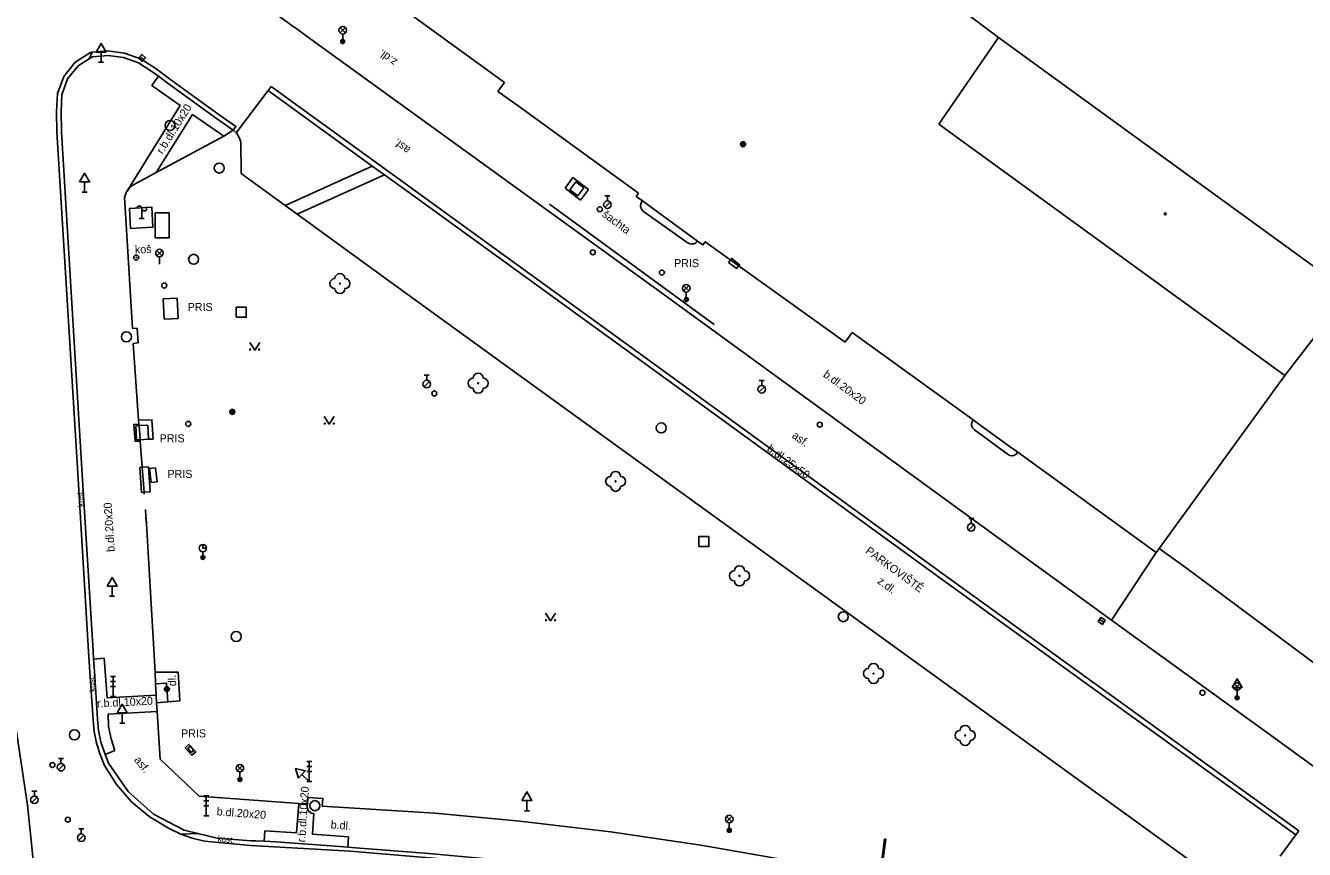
# Model space of a CAD drawing. Extents: x -599770 to -598493, y -1162076 to -1159209.
# Drawn here: x -599208.7 to -599144.8, y -1161563.7 to -1161522.6 of the extents above; entities that cross this region are included whole.
import ezdxf

# ---------------------------------------------------------------- set-up
doc = ezdxf.new("R2010")
doc.units = 0
doc.layers.add('Podklad', color=7, linetype='Continuous')

msp = doc.modelspace()

# ---------------------------------------------------------------- linework, layer by layer
at = {"layer": 'Podklad'}
for p, q in [((-599192.953, -1161522.94), (-599192.688, -1161522.675)), ((-599192.953, -1161522.675), (-599192.688, -1161522.94)), ((-599192.82, -1161522.995), (-599192.82, -1161523.37)), ((-599205.025, -1161524.41), (-599204.775, -1161524.41)), ((-599204.9, -1161523.901), (-599204.9, -1161524.41)), ((-599202.942, -1161524.105), (-599202.758, -1161524.275)), ((-599205.72, -1161530.381), (-599205.72, -1161530.89)), ((-599205.845, -1161530.89), (-599205.595, -1161530.89)), ((-599179.719, -1161531.656), (-599179.454, -1161531.391)), ((-599179.715, -1161531.082), (-599179.465, -1161531.082)), ((-599179.59, -1161531.332), (-599179.59, -1161531.082)), ((-599202.86, -1161532.21), (-599202.86, -1161531.71)), ((-599202.735, -1161532.21), (-599202.985, -1161532.21)), ((-599202.113, -1161534.07), (-599201.848, -1161533.805)), ((-599202.113, -1161533.805), (-599201.848, -1161534.07)), ((-599201.98, -1161534.125), (-599201.98, -1161534.5)), ((-599175.782, -1161535.83), (-599175.517, -1161535.565)), ((-599175.782, -1161535.565), (-599175.517, -1161535.83)), ((-599175.65, -1161535.885), (-599175.65, -1161536.26)), ((-599188.749, -1161540.616), (-599188.484, -1161540.351)), ((-599188.745, -1161540.043), (-599188.495, -1161540.043)), ((-599188.62, -1161540.293), (-599188.62, -1161540.043)), ((-599172.005, -1161540.302), (-599171.755, -1161540.302)), ((-599171.88, -1161540.552), (-599171.88, -1161540.302)), ((-599172.009, -1161540.876), (-599171.744, -1161540.611)), ((-599161.535, -1161547.203), (-599161.285, -1161547.203)), ((-599161.41, -1161547.453), (-599161.41, -1161547.203)), ((-599161.539, -1161547.776), (-599161.274, -1161547.511)), ((-599199.81, -1161548.865), (-599199.81, -1161549.04)), ((-599204.35, -1161550.571), (-599204.35, -1161551.08)), ((-599204.475, -1161551.08), (-599204.225, -1161551.08)), ((-599154.995, -1161552.243), (-599154.785, -1161552.377)), ((-599204.425, -1161555.09), (-599204.175, -1161555.09)), ((-599204.3, -1161556.09), (-599204.3, -1161555.09)), ((-599204.425, -1161555.34), (-599204.175, -1161555.34)), ((-599204.425, -1161555.59), (-599204.175, -1161555.59)), ((-599148.253, -1161555.72), (-599147.988, -1161555.455)), ((-599148.253, -1161555.455), (-599147.988, -1161555.72)), ((-599148.12, -1161555.641), (-599148.12, -1161556.15)), ((-599148.12, -1161555.775), (-599148.12, -1161556.15)), ((-599204.425, -1161556.09), (-599204.175, -1161556.09)), ((-599203.84, -1161556.911), (-599203.84, -1161557.42)), ((-599203.965, -1161557.42), (-599203.715, -1161557.42)), ((-599207.029, -1161559.756), (-599206.764, -1161559.491)), ((-599207.025, -1161559.183), (-599206.775, -1161559.183)), ((-599206.9, -1161559.433), (-599206.9, -1161559.183)), ((-599198.093, -1161559.8), (-599197.828, -1161559.535)), ((-599198.093, -1161559.535), (-599197.828, -1161559.8)), ((-599194.615, -1161559.33), (-599194.365, -1161559.33)), ((-599194.615, -1161559.58), (-599194.365, -1161559.58)), ((-599194.49, -1161560.33), (-599194.49, -1161559.33)), ((-599197.96, -1161559.855), (-599197.96, -1161560.23)), ((-599194.863, -1161559.983), (-599194.49, -1161560.33)), ((-599194.615, -1161559.83), (-599194.365, -1161559.83)), ((-599208.355, -1161560.812), (-599208.105, -1161560.812)), ((-599208.23, -1161561.062), (-599208.23, -1161560.812)), ((-599194.615, -1161560.33), (-599194.365, -1161560.33)), ((-599208.359, -1161561.386), (-599208.094, -1161561.121)), ((-599199.765, -1161561.05), (-599199.515, -1161561.05)), ((-599199.765, -1161561.3), (-599199.515, -1161561.3)), ((-599199.765, -1161561.55), (-599199.515, -1161561.55)), ((-599199.64, -1161562.05), (-599199.64, -1161561.05)), ((-599183.61, -1161561.281), (-599183.61, -1161561.79)), ((-599199.765, -1161562.05), (-599199.515, -1161562.05)), ((-599183.735, -1161561.79), (-599183.485, -1161561.79)), ((-599173.633, -1161562.34), (-599173.368, -1161562.075)), ((-599173.633, -1161562.075), (-599173.368, -1161562.34)), ((-599206.015, -1161562.703), (-599205.765, -1161562.703)), ((-599205.89, -1161562.953), (-599205.89, -1161562.703)), ((-599173.5, -1161562.395), (-599173.5, -1161562.77)), ((-599206.019, -1161563.276), (-599205.754, -1161563.011))]:
    msp.add_line(p, q, dxfattribs=at)
for points in [[(-599137.75, -1161564.29), (-599139.21, -1161563.25), (-599139.49, -1161563.04), (-599140.03, -1161562.64), (-599142.47, -1161560.9), (-599143.03, -1161560.49), (-599143.28, -1161560.31), (-599146.46, -1161558.01), (-599154.39, -1161552.27), (-599161.77, -1161546.92), (-599176.95, -1161535.88), (-599186.7, -1161528.83), (-599194.65, -1161523.08), (-599195.05, -1161522.79), (-599195.41, -1161522.53), (-599195.87, -1161522.2), (-599198.3, -1161520.43), (-599198.78, -1161520.08), (-599199.1, -1161519.85), (-599201.77, -1161517.89)], [(-599192.24, -1161519.96), (-599184.73, -1161525.41)], [(-599160.04, -1161523.17), (-599162.71, -1161521.16)], [(-599163.02, -1161527.5), (-599160.04, -1161523.17)], [(-599160.04, -1161523.17), (-599143.25, -1161535.36)], [(-599204.57, -1161523.84), (-599205.34, -1161523.91)], [(-599204.57, -1161523.84), (-599203.73, -1161523.95), (-599202.93, -1161524.24), (-599202.21, -1161524.69)], [(-599206.89, -1161526.87), (-599206.86, -1161526.03), (-599206.57, -1161525.24), (-599206.04, -1161524.58), (-599205.5, -1161524.24), (-599205.33, -1161524.13)], [(-599206.76, -1161525.12), (-599206.19, -1161524.41), (-599205.42, -1161523.92)], [(-599205.5, -1161524.24), (-599205.34, -1161523.91)], [(-599205.34, -1161523.91), (-599205.42, -1161523.92)], [(-599205.33, -1161524.13), (-599204.55, -1161524.07), (-599203.77, -1161524.17), (-599203.03, -1161524.44), (-599202.36, -1161524.86)], [(-599207.12, -1161526.87), (-599207.08, -1161525.97), (-599206.76, -1161525.12)], [(-599198.29, -1161527.8), (-599199.12, -1161527.21), (-599201.54, -1161525.46), (-599202.03, -1161525.1), (-599202.36, -1161524.86)], [(-599202.03, -1161525.1), (-599202.36, -1161525.56)], [(-599198.29, -1161527.8), (-599198.16, -1161527.62), (-599198.99, -1161527.03), (-599201.41, -1161525.28), (-599202.21, -1161524.69)], [(-599202.36, -1161525.56), (-599200.95, -1161526.57), (-599203.61, -1161530.86)], [(-599196.4, -1161525.61), (-599196.55, -1161525.81)], [(-599178.67, -1161538.45), (-599188.9, -1161531.04), (-599196.4, -1161525.61)], [(-599185.06, -1161525.86), (-599184.73, -1161525.41)], [(-599196.55, -1161525.81), (-599198.15, -1161527.93)], [(-599178.82, -1161538.65), (-599189.19, -1161531.14), (-599190.73, -1161530.03), (-599191.34, -1161529.59), (-599196.55, -1161525.81)], [(-599178.03, -1161530.95), (-599184.05, -1161526.59), (-599185.06, -1161525.86)], [(-599207.12, -1161526.87), (-599207.1, -1161527.89)], [(-599206.89, -1161526.87), (-599206.87, -1161527.88), (-599205.87, -1161544.45), (-599205.3, -1161553.82), (-599205.27, -1161554.22), (-599205.23, -1161554.83), (-599205.07, -1161557.22)], [(-599202.15, -1161529.92), (-599200.32, -1161527.02), (-599198.76, -1161528.1)], [(-599145.73, -1161540.05), (-599163.02, -1161527.5)], [(-599207.1, -1161527.89), (-599206.08, -1161544.67)], [(-599198.29, -1161527.8), (-599198.76, -1161528.1), (-599202.15, -1161529.92)], [(-599198.29, -1161527.8), (-599198.15, -1161527.93), (-599198.12, -1161527.96), (-599197.99, -1161528.16), (-599197.91, -1161528.38)], [(-599181.34, -1161541.97), (-599190.03, -1161535.67), (-599195.09, -1161532), (-599195.7, -1161531.56), (-599197.89, -1161529.97), (-599197.91, -1161528.38)], [(-599195.7, -1161531.56), (-599193.601, -1161530.609), (-599191.34, -1161529.59)], [(-599202.15, -1161529.92), (-599203.31, -1161530.54)], [(-599195.09, -1161532), (-599190.73, -1161530.03)], [(-599181.71, -1161530.7), (-599181.32, -1161530.17)], [(-599181.32, -1161530.17), (-599180.54, -1161530.76)], [(-599203.72, -1161531.17), (-599203.64, -1161530.92), (-599203.61, -1161530.86), (-599203.5, -1161530.71), (-599203.31, -1161530.54)], [(-599180.93, -1161531.29), (-599181.71, -1161530.7)], [(-599180.54, -1161530.76), (-599180.93, -1161531.29)], [(-599203.72, -1161531.17), (-599203.69, -1161531.67), (-599203.33, -1161537.71)], [(-599182.48, -1161531.5), (-599174.26, -1161537.5)], [(-599175.09, -1161533.34), (-599177.84, -1161531.33), (-599178.15, -1161531.11), (-599178.03, -1161530.95)], [(-599177.78, -1161531.86), (-599177.88, -1161531.75), (-599177.93, -1161531.61), (-599177.92, -1161531.46)], [(-599177.84, -1161531.33), (-599177.92, -1161531.46)], [(-599203.47, -1161531.71), (-599202.36, -1161531.65), (-599202.31, -1161532.65), (-599203.42, -1161532.71)], [(-599203.47, -1161531.71), (-599203.42, -1161532.71)], [(-599202.2, -1161531.92), (-599202.2, -1161533.18)], [(-599201.5, -1161531.92), (-599202.2, -1161531.92)], [(-599201.5, -1161533.18), (-599201.5, -1161531.92)], [(-599177.78, -1161531.86), (-599175.6, -1161533.41)], [(-599202.2, -1161533.18), (-599201.5, -1161533.18)], [(-599175.19, -1161533.44), (-599175.33, -1161533.49), (-599175.47, -1161533.48), (-599175.6, -1161533.41)], [(-599175.09, -1161533.34), (-599175.19, -1161533.44)], [(-599175.09, -1161533.34), (-599174.82, -1161533.53), (-599174.7, -1161533.37), (-599167.71, -1161538.39)], [(-599201.79, -1161536.22), (-599201.09, -1161536.19)], [(-599201.75, -1161537.24), (-599201.79, -1161536.22)], [(-599201.09, -1161536.19), (-599201.05, -1161537.21)], [(-599201.05, -1161537.21), (-599201.75, -1161537.24)], [(-599203.33, -1161537.71), (-599203.09, -1161537.69), (-599203.05, -1161538.42), (-599203.3, -1161538.45)], [(-599167.36, -1161537.9), (-599167.71, -1161538.39)], [(-599161.31, -1161542.27), (-599167.36, -1161537.9)], [(-599145.73, -1161540.05), (-599143.65, -1161537.36)], [(-599203.3, -1161538.45), (-599203.02, -1161542.29), (-599203.01, -1161542.48), (-599203, -1161542.55)], [(-599197.47, -1161538.405), (-599197.22, -1161538.78), (-599196.97, -1161538.405)], [(-599162.82, -1161549.96), (-599178.67, -1161538.45)], [(-599145.19, -1161563), (-599162.97, -1161550.16), (-599178.82, -1161538.65)], [(-599145.73, -1161540.05), (-599152.02, -1161548.69), (-599152.17, -1161548.9)], [(-599203.02, -1161542.29), (-599202.36, -1161542.26), (-599202.3, -1161543.23), (-599202.52, -1161543.24)], [(-599193.74, -1161542.105), (-599193.49, -1161542.48), (-599193.24, -1161542.105)], [(-599148.63, -1161565.61), (-599164.3, -1161554.29), (-599181.34, -1161541.97)], [(-599161.31, -1161542.27), (-599161.37, -1161542.39)], [(-599160.91, -1161542.56), (-599161.31, -1161542.27)], [(-599203.01, -1161542.48), (-599203.256, -1161542.497), (-599203.196, -1161543.341), (-599202.94, -1161543.33)], [(-599202.56, -1161542.53), (-599203, -1161542.55), (-599203.16, -1161542.56)], [(-599203.16, -1161542.56), (-599203.12, -1161543.27)], [(-599203.12, -1161543.27), (-599202.94, -1161543.26), (-599202.52, -1161543.24), (-599202.56, -1161542.53)], [(-599203, -1161542.55), (-599202.94, -1161543.26)], [(-599161.25, -1161542.77), (-599161.34, -1161542.67), (-599161.39, -1161542.53), (-599161.37, -1161542.39)], [(-599161.25, -1161542.77), (-599159.61, -1161543.97)], [(-599160.91, -1161542.56), (-599159.51, -1161543.58)], [(-599202.94, -1161543.26), (-599202.94, -1161543.33), (-599202.84, -1161544.64)], [(-599159.51, -1161543.58), (-599159.08, -1161543.89), (-599152.17, -1161548.9)], [(-599159.18, -1161544), (-599159.33, -1161544.06), (-599159.48, -1161544.05), (-599159.61, -1161543.97)], [(-599159.08, -1161543.89), (-599159.18, -1161544)], [(-599206.08, -1161544.67), (-599205.53, -1161553.84), (-599205.46, -1161554.85), (-599205.3, -1161557.25)], [(-599202.53, -1161544.62), (-599202.84, -1161544.64), (-599202.96, -1161544.65)], [(-599202.96, -1161544.65), (-599202.88, -1161545.89)], [(-599202.84, -1161544.64), (-599202.75, -1161545.88)], [(-599202.45, -1161545.86), (-599202.53, -1161544.62)], [(-599202.47, -1161544.7), (-599202.17, -1161544.67)], [(-599202.4, -1161545.4), (-599202.47, -1161544.7)], [(-599202.17, -1161544.67), (-599202.1, -1161545.37)], [(-599207.71, -1161570.05), (-599208.393, -1161563.275), (-599208.57, -1161561.52), (-599209.33, -1161556.5), (-599210.84, -1161549.96), (-599210.928, -1161549.677), (-599212.34, -1161545.14)], [(-599202.1, -1161545.37), (-599202.4, -1161545.4)], [(-599202.88, -1161545.89), (-599202.75, -1161545.88), (-599202.45, -1161545.86)], [(-599202.75, -1161545.88), (-599202.742, -1161545.981)], [(-599202.679, -1161546.744), (-599202.637, -1161547.38)], [(-599202.09, -1161556.83), (-599202.12, -1161556.4), (-599202.14, -1161556.02), (-599202.17, -1161555.46), (-599202.2, -1161554.88), (-599202.65, -1161547.18)], [(-599199.81, -1161548.49), (-599199.81, -1161548.678), (-599199.622, -1161548.678)], [(-599152.02, -1161548.69), (-599150.72, -1161549.63)], [(-599152.17, -1161548.9), (-599154.39, -1161552.27)], [(-599145.04, -1161562.8), (-599162.82, -1161549.96)], [(-599138.23, -1161558.76), (-599138.53, -1161558.58), (-599139.13, -1161558.13), (-599144.01, -1161554.61), (-599150.72, -1161549.63)], [(-599182.68, -1161551.925), (-599182.43, -1161552.3), (-599182.18, -1161551.925)], [(-599205.27, -1161554.22), (-599204.74, -1161554.18)], [(-599202.14, -1161556.02), (-599204.6, -1161556.16), (-599204.74, -1161554.18)], [(-599202.2, -1161554.88), (-599201.05, -1161554.87), (-599200.96, -1161556.31), (-599201.56, -1161556.36), (-599202.12, -1161556.4)], [(-599202.17, -1161555.46), (-599201.621, -1161555.42), (-599201.591, -1161555.884), (-599201.56, -1161556.36)], [(-599204.55, -1161556.97), (-599202.09, -1161556.83)], [(-599204.21, -1161558.79), (-599204.4, -1161558.2), (-599204.52, -1161557.59), (-599204.55, -1161556.97)], [(-599199.99, -1161561.07), (-599201.94, -1161559.21), (-599202.09, -1161556.83)], [(-599204.72, -1161559.53), (-599204.95, -1161558.98), (-599205.13, -1161558.42), (-599205.24, -1161557.84), (-599205.3, -1161557.25)], [(-599204.7, -1161558.99), (-599204.91, -1161558.35), (-599205.02, -1161557.79), (-599205.07, -1161557.22)], [(-599204.21, -1161558.79), (-599204.7, -1161558.99)], [(-599199.09, -1161563.17), (-599200.06, -1161562.93), (-599200.75, -1161562.76), (-599202.27, -1161561.96), (-599203.55, -1161560.83), (-599204.52, -1161559.42), (-599204.7, -1161558.99)], [(-599200.42, -1161558.56), (-599200.56, -1161558.66)], [(-599200.56, -1161558.66), (-599200.4, -1161558.88)], [(-599200.26, -1161558.78), (-599200.42, -1161558.56)], [(-599200.4, -1161558.88), (-599200.26, -1161558.78)], [(-599201.53, -1161562.67), (-599202.5, -1161562.08), (-599203.37, -1161561.35), (-599204.12, -1161560.49), (-599204.72, -1161559.53)], [(-599195.01, -1161561.44), (-599199.99, -1161561.07)], [(-599195.13, -1161562.9), (-599195.01, -1161561.44)], [(-599194.58, -1161561.45), (-599195.01, -1161561.44)], [(-599194.6, -1161561.62), (-599194.58, -1161561.45)], [(-599194.56, -1161561.14), (-599194.58, -1161561.45)], [(-599194.56, -1161561.14), (-599193.81, -1161561.19), (-599193.84, -1161561.56)], [(-599194.26, -1161561.94), (-599194.42, -1161561.89), (-599194.55, -1161561.78), (-599194.6, -1161561.62)], [(-599194.33, -1161562.96), (-599194.26, -1161561.94)], [(-599193.84, -1161561.56), (-599188.21, -1161561.92), (-599183.97, -1161562.31)], [(-599200.91, -1161562.97), (-599201.53, -1161562.67)], [(-599196.74, -1161563.32), (-599196.71, -1161562.79)], [(-599196.71, -1161562.79), (-599195.13, -1161562.9)], [(-599174.93, -1161563.51), (-599179.44, -1161562.85), (-599183.97, -1161562.31)], [(-599145.04, -1161562.8), (-599145.19, -1161563)], [(-599200.06, -1161562.93), (-599200.91, -1161562.97)], [(-599199.72, -1161563.32), (-599200.35, -1161563.17), (-599200.91, -1161562.97)], [(-599197.42, -1161563.53), (-599198.68, -1161563.42), (-599199.72, -1161563.32)], [(-599199.09, -1161563.17), (-599197.4, -1161563.29), (-599197.17, -1161563.29), (-599196.74, -1161563.32), (-599196.17, -1161563.35), (-599193.19, -1161563.57), (-599192.57, -1161563.62), (-599192.18, -1161563.65)], [(-599192.53, -1161563.09), (-599194.33, -1161562.96)], [(-599192.57, -1161563.62), (-599192.53, -1161563.09)], [(-599165.94, -1161564.79), (-599165.74, -1161563.21)], [(-599165.94, -1161564.79), (-599165.89, -1161564.8), (-599165.68, -1161563.22), (-599165.74, -1161563.21)], [(-599145.19, -1161563), (-599145.97, -1161564.06)], [(-599197.42, -1161563.53), (-599192.45, -1161563.82), (-599187.5, -1161564.23)], [(-599192.18, -1161563.65), (-599188.52, -1161563.93), (-599184.88, -1161564.27), (-599181.23, -1161564.69)], [(-599174.93, -1161563.51), (-599170.44, -1161564.29), (-599165.97, -1161565.18)]]:
    msp.add_lwpolyline(points, dxfattribs=at)
for points in [[(-599205.15, -1161523.901), (-599204.65, -1161523.901), (-599204.9, -1161523.468)], [(-599203.027, -1161524.197), (-599202.843, -1161524.367), (-599202.673, -1161524.183), (-599202.857, -1161524.013)], [(-599205.97, -1161530.381), (-599205.47, -1161530.381), (-599205.72, -1161529.948)], [(-599181.074, -1161531.08), (-599180.77, -1161530.684), (-599181.166, -1161530.38), (-599181.47, -1161530.776)], [(-599173.533, -1161534.402), (-599173.142, -1161534.713), (-599172.987, -1161534.518), (-599173.378, -1161534.207)], [(-599198.14, -1161537.14), (-599197.64, -1161537.14), (-599197.64, -1161536.64), (-599198.14, -1161536.64)], [(-599175.02, -1161548.6), (-599174.52, -1161548.6), (-599174.52, -1161548.1), (-599175.02, -1161548.1)], [(-599204.6, -1161550.571), (-599204.1, -1161550.571), (-599204.35, -1161550.138)], [(-599155.063, -1161552.348), (-599154.852, -1161552.483), (-599154.717, -1161552.272), (-599154.928, -1161552.137)], [(-599148.37, -1161555.641), (-599147.87, -1161555.641), (-599148.12, -1161555.208)], [(-599204.09, -1161556.911), (-599203.59, -1161556.911), (-599203.84, -1161556.478)], [(-599200.691, -1161558.65), (-599200.354, -1161559.019), (-599200.169, -1161558.85), (-599200.506, -1161558.481)], [(-599195.033, -1161560.166), (-599194.692, -1161559.8), (-599195.18, -1161559.688)], [(-599183.86, -1161561.281), (-599183.36, -1161561.281), (-599183.61, -1161560.848)]]:
    msp.add_lwpolyline(points, close=True, dxfattribs=at)
for centre, radius in [((-599192.82, -1161522.808), 0.188), ((-599192.82, -1161523.37), 0.1), ((-599192.82, -1161523.37), 0.0723), ((-599192.82, -1161523.37), 0.0438), ((-599201.45, -1161527.56), 0.25), ((-599172.81, -1161528.5), 0.125), ((-599172.81, -1161528.5), 0.1), ((-599172.81, -1161528.5), 0.075), ((-599172.81, -1161528.5), 0.05), ((-599172.81, -1161528.5), 0.025), ((-599198.99, -1161529.69), 0.25), ((-599179.59, -1161531.52), 0.188), ((-599179.97, -1161531.75), 0.125), ((-599151.71, -1161531.98), 0.045), ((-599151.71, -1161531.98), 0.0199), ((-599203.14, -1161534.16), 0.125), ((-599201.98, -1161533.938), 0.188), ((-599200.27, -1161534.25), 0.25), ((-599180.32, -1161533.9), 0.125), ((-599203.14, -1161534.16), 0.0152), ((-599176.87, -1161534.91), 0.125), ((-599201.74, -1161535.56), 0.125), ((-599192.96, -1161535.46), 0.025), ((-599175.65, -1161535.698), 0.188), ((-599175.65, -1161536.26), 0.1), ((-599175.65, -1161536.26), 0.0723), ((-599175.65, -1161536.26), 0.0438), ((-599203.63, -1161538.12), 0.25), ((-599197.445, -1161538.755), 0.025), ((-599196.995, -1161538.755), 0.025), ((-599188.62, -1161540.48), 0.188), ((-599186.05, -1161540.44), 0.025), ((-599188.24, -1161540.95), 0.125), ((-599171.88, -1161540.74), 0.188), ((-599200.54, -1161542.47), 0.125), ((-599198.34, -1161541.87), 0.125), ((-599198.34, -1161541.87), 0.1), ((-599198.34, -1161541.87), 0.075), ((-599198.34, -1161541.87), 0.05), ((-599198.34, -1161541.87), 0.025), ((-599193.715, -1161542.455), 0.025), ((-599193.265, -1161542.455), 0.025), ((-599176.9, -1161542.67), 0.25), ((-599168.98, -1161542.51), 0.125), ((-599179.18, -1161545.34), 0.025), ((-599161.41, -1161547.64), 0.188), ((-599199.81, -1161548.678), 0.188), ((-599199.81, -1161549.14), 0.1), ((-599199.81, -1161549.14), 0.0723), ((-599199.81, -1161549.14), 0.0438), ((-599172.99, -1161550.06), 0.025), ((-599167.8, -1161552.1), 0.25), ((-599182.655, -1161552.275), 0.025), ((-599182.205, -1161552.275), 0.025), ((-599198.14, -1161553.09), 0.25), ((-599166.29, -1161554.94), 0.025), ((-599201.61, -1161555.72), 0.125), ((-599201.61, -1161555.72), 0.1), ((-599201.61, -1161555.72), 0.075), ((-599201.61, -1161555.72), 0.05), ((-599201.61, -1161555.72), 0.025), ((-599149.85, -1161555.9), 0.125), ((-599148.12, -1161555.587), 0.188), ((-599148.12, -1161556.15), 0.1), ((-599148.12, -1161556.15), 0.0723), ((-599148.12, -1161556.15), 0.0438), ((-599206.23, -1161558), 0.25), ((-599161.71, -1161558.03), 0.025), ((-599207.33, -1161559.51), 0.125), ((-599206.9, -1161559.62), 0.188), ((-599197.96, -1161559.668), 0.188), ((-599197.96, -1161560.23), 0.1), ((-599197.96, -1161560.23), 0.0723), ((-599197.96, -1161560.23), 0.0438), ((-599208.23, -1161561.25), 0.188), ((-599194.21, -1161561.54), 0.25), ((-599206.56, -1161562.24), 0.125), ((-599173.5, -1161562.207), 0.188), ((-599173.5, -1161562.77), 0.1), ((-599173.5, -1161562.77), 0.0723), ((-599173.5, -1161562.77), 0.0438), ((-599205.89, -1161563.14), 0.188)]:
    msp.add_circle(centre, radius, dxfattribs=at)
for centre, radius, start, end in [((-599202.985, -1161531.71), 0.125, 0, 180), ((-599202.735, -1161531.71), 0.125, 180, 0), ((-599193.21, -1161535.46), 0.25, 90, 270), ((-599192.96, -1161535.21), 0.25, 0, 180), ((-599192.71, -1161535.46), 0.25, 270, 90), ((-599192.96, -1161535.71), 0.25, 180, 0), ((-599186.3, -1161540.44), 0.25, 90, 270), ((-599186.05, -1161540.19), 0.25, 0, 180), ((-599185.8, -1161540.44), 0.25, 270, 90), ((-599186.05, -1161540.69), 0.25, 180, 0), ((-599179.18, -1161545.09), 0.25, 0, 180), ((-599179.43, -1161545.34), 0.25, 90, 270), ((-599178.93, -1161545.34), 0.25, 270, 90), ((-599179.18, -1161545.59), 0.25, 180, 0), ((-599173.24, -1161550.06), 0.25, 90, 270), ((-599172.99, -1161549.81), 0.25, 0, 180), ((-599172.74, -1161550.06), 0.25, 270, 90), ((-599172.99, -1161550.31), 0.25, 180, 0), ((-599166.29, -1161554.69), 0.25, 0, 180), ((-599166.54, -1161554.94), 0.25, 90, 270), ((-599166.04, -1161554.94), 0.25, 270, 90), ((-599166.29, -1161555.19), 0.25, 180, 0), ((-599161.71, -1161557.78), 0.25, 0, 180), ((-599161.96, -1161558.03), 0.25, 90, 270), ((-599161.71, -1161558.28), 0.25, 180, 0), ((-599161.46, -1161558.03), 0.25, 270, 90)]:
    msp.add_arc(centre, radius, start, end, dxfattribs=at)

# ---------------------------------------------------------------- texts
for s, height, rotation, p in [('z.dl.', 0.4, 144, (-599190.06, -1161524.31)), ('r.b.dl.10x20', 0.4, 58, (-599201.83, -1161529.02)), ('asf.', 0.4, 142.5, (-599189.402, -1161528.712)), ('šachta', 0.4, 323.27031, (-599179.887, -1161532.074)), ('koš', 0.4, 1.93497, (-599203.2, -1161533.96)), ('b.dl.20x20', 0.4, 323.71279, (-599168.84, -1161540.08)), ('asf.', 0.4, 324.13708, (-599170.4, -1161543.13)), ('b.dl.25x50', 0.4, 323.71279, (-599171.65, -1161543.78)), ('kost.', 0.3, 96.04705, (-599205.741, -1161546.597)), ('b.dl.20x20', 0.4, 93.75838, (-599204.214, -1161548.85)), ('PARKOVIŠTĚ', 0.4, 323.74448, (-599166.73, -1161548.89)), ('z.dl.', 0.4, 323.82042, (-599166.13, -1161550.4)), ('kost.', 0.3, 94, (-599205.187, -1161555.842)), ('dl.', 0.4, 90.97932, (-599201.141, -1161555.569)), ('r.b.dl.10x20', 0.4, 3, (-599205.09, -1161556.639)), ('asf.', 0.4, 309, (-599203.27, -1161559.27)), ('r.b.dl.10x20', 0.4, 86, (-599194.7, -1161563.38)), ('b.dl.20x20', 0.4, 355.69558, (-599199.13, -1161562.02)), ('b.dl.', 0.4, 356, (-599193.43, -1161562.68)), ('kost.', 0.3, 353.90947, (-599199.08, -1161563.33))]:
    msp.add_text(s, height=height, rotation=rotation, dxfattribs=at).set_placement(p)
for p in [(-599176.26, -1161534.64), (-599200.57, -1161536.83), (-599201.97, -1161543.39), (-599201.58, -1161545.17), (-599200.9, -1161558.13)]:
    msp.add_text('PRIS', height=0.4, dxfattribs=at).set_placement(p)

doc.saveas('drawing.dxf')
